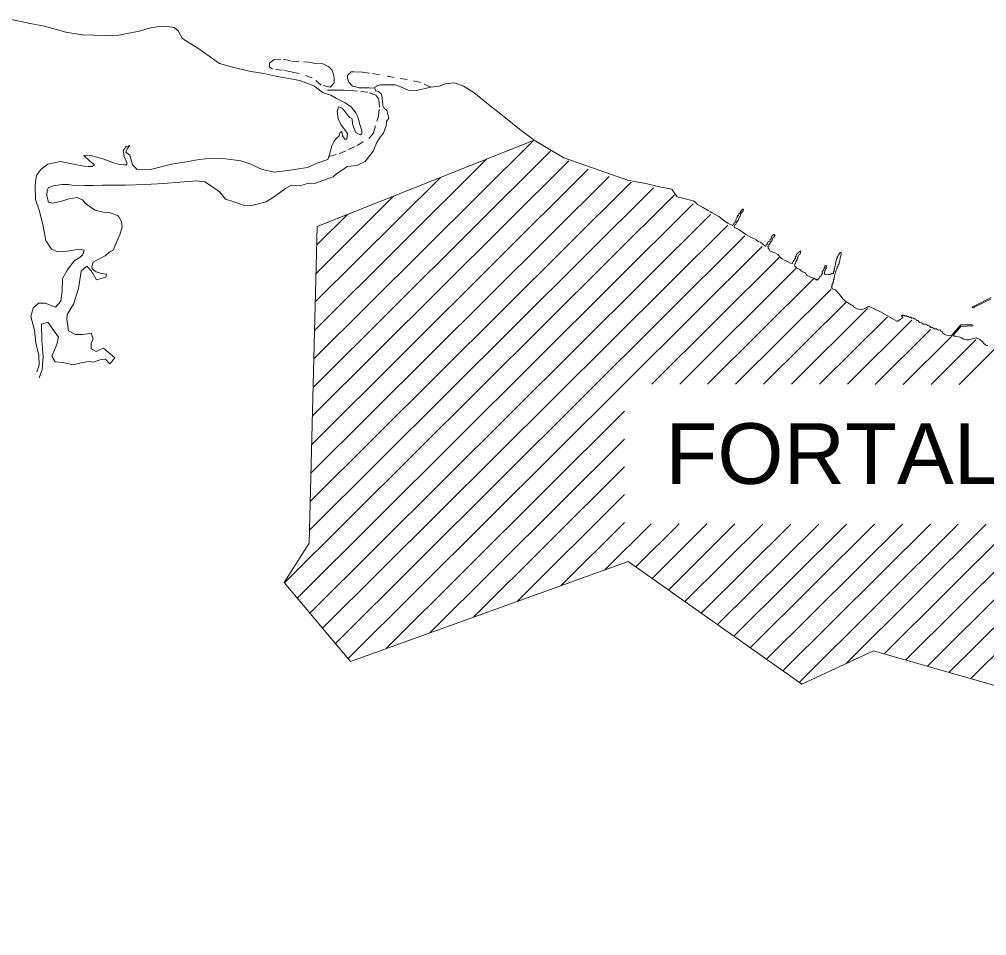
# Model space of a CAD drawing. Extents: x 47169 to 972804, y 7447977 to 9608469.
# Drawn here: x 541676 to 552551, y 9582149 to 9592447 of the extents above; entities that cross this region are included whole.
import ezdxf

# ---------------------------------------------------------------- set-up
doc = ezdxf.new("R2010")
doc.units = 0
doc.header["$LTSCALE"] = 270
doc.linetypes.add('DOTTED', pattern=[1.5, 0.3, -1.2])
doc.layers.add('1', color=7, linetype='Continuous', lineweight=13)
doc.layers.add('3', color=7, linetype='Continuous')

msp = doc.modelspace()

# ---------------------------------------------------------------- linework, layer by layer
at = {"layer": '1'}
for p, q in [((544987.1, 9588631.2), (547455.8, 9591086.2)), ((544978.1, 9588310.7), (547647.9, 9590965.6)), ((544970.2, 9587990.1), (547854.4, 9590857.2)), ((544995, 9588951.8), (546932.7, 9590878.7)), ((544962.2, 9587669.5), (548072, 9590762.1)), ((544954.3, 9587347.9), (548305.2, 9590681.2)), ((545002.9, 9589272.3), (546409.5, 9590671.1)), ((544937.4, 9586706.7), (548804.8, 9590552.8)), ((544946.4, 9587027.3), (548555, 9590617)), ((544655, 9586113.3), (549042.4, 9590476.4)), ((545010.9, 9589592.9), (545886.3, 9590463.5)), ((544798.2, 9585943), (549251.2, 9590372.4)), ((544941.4, 9585773.8), (549447.7, 9590255.1)), ((545018.8, 9589913.4), (545364.3, 9590256)), ((545084.5, 9585603.5), (549640.8, 9590134.5)), ((545228.8, 9585433.2), (549834, 9590013.9)), ((545372, 9585264), (550027.2, 9589893.3)), ((548786.2, 9588346.7), (550217, 9589769.4)), ((549100.5, 9588346.5), (550406.8, 9589645.5)), ((549413.7, 9588346.4), (550612.2, 9589538.2)), ((549727.9, 9588346.2), (550804.3, 9589416.5)), ((550043.3, 9588346), (550973, 9589270.5)), ((550356.5, 9588345.9), (551211.7, 9589196.3)), ((550670.8, 9588345.7), (551434.9, 9589105.6)), ((550985, 9588345.6), (551710.3, 9589066.7)), ((551299.3, 9588345.4), (551919, 9588961.6)), ((551613.6, 9588345.2), (552155.5, 9588884.1)), ((551926.7, 9588345.1), (552428.7, 9588844.2)), ((552241, 9588344.9), (552651.8, 9588753.4)), ((545798.5, 9585375.5), (548481.2, 9588043.3)), ((546290.5, 9585552.1), (548481, 9587730.5)), ((546782.5, 9585729.8), (548480.9, 9587418.8)), ((547274.5, 9585906.4), (548480.7, 9587106)), ((547766.5, 9586083.1), (548480.6, 9586793.1)), ((548258.6, 9586259.7), (548778, 9586776.2)), ((548606.2, 9586292.7), (549092.3, 9586776.1)), ((548789.3, 9586163.2), (549405.4, 9586775.9)), ((548973.6, 9586033.8), (549719.7, 9586775.8)), ((549157.9, 9585903.3), (550035.1, 9586775.6)), ((549341, 9585773.9), (550348.2, 9586775.5)), ((549525.3, 9585644.5), (550662.5, 9586775.3)), ((549709.6, 9585515), (550976.8, 9586775.1)), ((549892.7, 9585385.6), (551289.9, 9586775)), ((550077, 9585255.1), (551605.3, 9586774.8)), ((550261.3, 9585125.6), (551919.6, 9586774.6)), ((550444.4, 9584996.2), (552232.7, 9586774.5)), ((550970.9, 9585207.1), (552547, 9586774.3)), ((551397.4, 9585318.5), (552861.2, 9586774.1)), ((551641.6, 9585248.7), (553175.5, 9586774)), ((551884.8, 9585179), (553489.6, 9586773.8)), ((552129.1, 9585109.2), (553803.9, 9586773.6)), ((552373.3, 9585038.3), (554117.4, 9586773.4))]:
    msp.add_line(p, q, dxfattribs=at)
for points in [[(541996.8, 9590821.7), (542139.6, 9590851), (542284, 9590820), (542401.7, 9590795.6), (542449.4, 9590794.5), (542495, 9590793.3), (542520.5, 9590813.2), (542462.8, 9590858.6), (542399.5, 9590918.3), (542467.3, 9590919.4), (542626.1, 9590877.3), (542733.8, 9590834.2), (542788.2, 9590818.6), (542849.2, 9590814.2), (542882.6, 9590813.1), (542884.8, 9590842.9), (542859.3, 9590889.4), (542843.8, 9590970.1), (542874.9, 9591017.6), (542919.3, 9591028.6), (542893.8, 9591004.3), (542873.8, 9590955.7), (542919.2, 9590919.2), (542948.1, 9590814.2), (542999.2, 9590758.9), (543165.7, 9590762.1), (543385.6, 9590819.5), (543532.2, 9590841.5), (543697.7, 9590873.5), (543839.9, 9590888.9), (543994.2, 9590881.1), (544167.4, 9590857.8), (544265.2, 9590823.5), (544407.3, 9590761.6), (544542.8, 9590729.4), (544719.3, 9590752.6), (544914.8, 9590782.3), (545022.5, 9590832), (545142.5, 9590872.9), (545161.4, 9590928.1), (545189.2, 9591024.3), (545214.8, 9591077.3), (545240.3, 9591110.5), (545270.3, 9591139.2), (545277, 9591172.4), (545301.4, 9591186.7), (545307, 9591139.2), (545334.7, 9591099.4), (545358, 9591102.7), (545365.8, 9591163.5), (545290.4, 9591266.3), (545261.5, 9591328.2), (545247.1, 9591411.2), (545264.9, 9591465.3), (545306, 9591448.7), (545341.5, 9591403.4), (545372.6, 9591361.3), (545392.6, 9591344.8), (545417, 9591330.4), (545421.4, 9591272.9), (545455.8, 9591178.9), (545508, 9591151.3), (545524.6, 9591162.3), (545524.7, 9591197.7), (545501.4, 9591278.4), (545485.9, 9591340.3), (545458.1, 9591397.8), (545406, 9591464.1), (545331.6, 9591511.7), (545242.8, 9591557.1), (545176.1, 9591593.6), (545091.8, 9591621.2), (544985.2, 9591699.8), (544830.8, 9591758.4), (544559.9, 9591807.2), (544425.5, 9591837.1), (544280.1, 9591861.5), (544226.8, 9591872.6), (544102.4, 9591903.6), (543924.7, 9591952.3), (543811.5, 9592033), (543681.6, 9592123.7), (543603.9, 9592171.3), (543548.4, 9592204.5), (543505.1, 9592235.4), (543459.6, 9592319.5), (543415.2, 9592356), (543364.1, 9592364.8), (543267.5, 9592370.4), (543135.3, 9592347.2), (543040.9, 9592319.7), (542794.3, 9592271.1), (542638.9, 9592265.7), (542382.3, 9592272.4), (542198, 9592302.3), (541957.1, 9592371), (541796, 9592402), (541586.2, 9592447.4)], [(549250.1, 9590407.7), (549072.4, 9590454.2), (549012.5, 9590540.5), (548873.7, 9590563.8), (548719.3, 9590602.6), (548527.2, 9590638), (548409.5, 9590679), (548043.1, 9590804.1), (547798.9, 9590889.3), (547575.7, 9591023.2), (547463.6, 9591089.5), (547300.4, 9591212.3), (547123.9, 9591357.2), (546970.7, 9591474.5), (546786.4, 9591624.9), (546667.6, 9591695.7), (546568.8, 9591733.3), (546464.4, 9591723.4), (546396.7, 9591695.8), (546302.2, 9591684.8), (546142.3, 9591648.4), (546046.8, 9591652.9), (545965.8, 9591688.3), (545900.2, 9591710.4), (545794.8, 9591711.6), (545734.8, 9591710.5), (545694.8, 9591700.6), (545694.8, 9591696.1), (545673.7, 9591686.2), (545672.6, 9591675.1), (545678.1, 9591644.2), (545713.7, 9591635.3), (545748.1, 9591605.5), (545753.6, 9591559), (545758, 9591530.3), (545758, 9591528.1), (545762.4, 9591480.6), (545776.9, 9591448.5), (545805.7, 9591421.9), (545827.9, 9591337.9), (545802.3, 9591299.2), (545799, 9591251.7), (545771.2, 9591168.8), (545732.3, 9591122.4), (545694.5, 9591061.6), (545652.3, 9590965.5), (545563.4, 9590851.7), (545471.2, 9590805.3), (545364.6, 9590792.1), (545245.7, 9590713.6), (545203.5, 9590676.1), (545100.2, 9590640.8), (544993.6, 9590604.3), (544926.9, 9590605.5), (544828.1, 9590575.7), (544735.9, 9590585.7), (544667, 9590545.9), (544554.8, 9590465.2), (544451.5, 9590396.8), (544289.4, 9590353.7), (544195, 9590360.4), (544086.2, 9590396.9), (543991.8, 9590425.7), (543924.1, 9590509.7), (543846.4, 9590565.1), (543760.9, 9590620.3), (543666.5, 9590633.7), (543478.8, 9590616.1), (543296.7, 9590602.9), (543090.1, 9590590.8), (542868, 9590585.4), (542659.2, 9590583.3), (542611.5, 9590583.3), (542504.9, 9590578.9), (542411.6, 9590578.9), (542263.9, 9590583.4), (542232.8, 9590592.3), (542158.4, 9590592.3), (542054, 9590575.8), (542001.8, 9590557), (541987.4, 9590526.1), (541986.2, 9590463.1), (542001.8, 9590391.2), (542049.5, 9590382.3), (542165, 9590406.6), (542232.7, 9590432), (542327.2, 9590446.3), (542383.8, 9590417.6), (542417.1, 9590383.3), (542477, 9590336.8), (542529.2, 9590301.4), (542620.3, 9590280.4), (542692.4, 9590271.5), (542724.6, 9590266), (542777.9, 9590242.8), (542795.7, 9590228.4), (542823.4, 9590176.4), (542830.1, 9590110.1), (542806.7, 9590029.4), (542760, 9589923.3), (542730, 9589854.8)], [(557927.8, 9588750.4), (558195.3, 9588397.6), (559210.8, 9585590.4), (558211.2, 9585310.2), (556763.8, 9586414.3), (554189.6, 9582179.8), (553295.6, 9582149.4), (553111.7, 9582905.6), (553425.9, 9582840.2), (553310.4, 9584770.3), (551280.8, 9585351.7), (550474.4, 9584975.2), (548519.6, 9586353.5), (545398.6, 9585231.9), (544651.7, 9586116.6), (544934, 9586558.6), (545024.4, 9590121.2), (547463.6, 9591089.5)], [(541872.1, 9588485.6), (541898.8, 9588559.6), (541893.3, 9588671.3), (541861.2, 9588811.7), (541845.7, 9588953.2), (541805.8, 9589106.8), (541830.2, 9589200.8), (541889.1, 9589256), (541966.8, 9589256), (542081.2, 9589211.7), (542141.2, 9589280.2), (542155.7, 9589391.9), (542161.3, 9589536.7), (542215.8, 9589632.8), (542293.5, 9589732.3), (542355.7, 9589770.9), (542390.2, 9589805.2), (542404.6, 9589854.9), (542352.4, 9589863.8), (542213.6, 9589840.6), (542109.2, 9589836.2), (542037.1, 9589863.9), (541972.7, 9589961.2), (541941.7, 9590121.5), (541901.8, 9590291.8), (541858.5, 9590423.3), (541853, 9590577), (541859.7, 9590643.3), (541868.6, 9590693), (541911.9, 9590754.9), (541937.5, 9590775.9), (541996.8, 9590821.7)], [(550106, 9589863.5), (550094.9, 9589875.6), (550089.4, 9589882.3), (550093.8, 9589884.5), (550091.6, 9589893.3), (550103.8, 9589899.9), (550103.8, 9589914.3), (550116, 9589933.1), (550120.5, 9589938.6), (550128.3, 9589950.8), (550134.9, 9589958.5), (550140.5, 9589965.1), (550143.8, 9589979.5), (550149.4, 9589996.1), (550157.2, 9590000.5), (550166.1, 9590010.4), (550172.7, 9590018.2), (550164.9, 9590018.2), (550165, 9590029.2), (550152.7, 9590030.3), (550149.4, 9590021.5), (550139.4, 9590016), (550134.9, 9590001.6), (550131.6, 9590000.5), (550123.8, 9589972.9), (550117.2, 9589975.1), (550112.7, 9589955.2), (550093.8, 9589949.7), (550087.2, 9589933.1), (550083.8, 9589933.1), (550081.6, 9589913.2), (550071.6, 9589913.2), (550067.2, 9589897.7), (550059.4, 9589900), (550036.1, 9589919.9), (550008.3, 9589942), (549983.9, 9589952), (549958.4, 9589969.7), (549933.9, 9589986.2), (549905.1, 9589997.3), (549869.6, 9590012.8), (549841.8, 9590029.4), (549816.3, 9590047.1), (549766.3, 9590084.7), (549734.1, 9590100.2), (549718.6, 9590104.6), (549714.1, 9590116.8), (549720.8, 9590137.8), (549733, 9590143.3), (549735.2, 9590158.8), (549751.9, 9590185.3), (549761.9, 9590194.1), (549763, 9590205.2), (549765.3, 9590208.5), (549770.8, 9590227.3), (549780.8, 9590236.1), (549787.5, 9590260.5), (549803.1, 9590284.8), (549810.8, 9590284.8), (549813.1, 9590296.9), (549816.4, 9590309.1), (549811.9, 9590312.4), (549800.8, 9590312.4), (549797.5, 9590296.9), (549784.2, 9590293.6), (549781.9, 9590277), (549769.7, 9590266), (549761.9, 9590243.9), (549755.3, 9590245), (549754.2, 9590240.6), (549747.5, 9590226.2), (549743.1, 9590215.2), (549739.7, 9590210.7), (549733, 9590195.2), (549730.8, 9590179.8), (549723, 9590176.5), (549719.7, 9590158.8), (549710.8, 9590158.8), (549706.4, 9590144.4), (549695.3, 9590132.3), (549665.3, 9590146.7), (549646.4, 9590152.2), (549607.6, 9590177.6), (549578.7, 9590200.9), (549539.8, 9590231.8), (549517.6, 9590242.9), (549464.3, 9590273.9), (549446.6, 9590282.7), (549421, 9590300.4), (549356.7, 9590338.1), (549301.1, 9590367.9), (549280.1, 9590385.6), (549268.9, 9590397.8), (549250.1, 9590407.7)], [(542730, 9589854.8), (542686.7, 9589829.4), (542641.1, 9589789.6), (542553.4, 9589744.3), (542505.6, 9589716.7), (542491.2, 9589670.3), (542494.5, 9589642.7), (542540, 9589608.3), (542595.5, 9589592.9), (542655.5, 9589585.1), (542656.6, 9589579.6), (542646.6, 9589550.8), (542544.4, 9589521), (542487.8, 9589618.3), (542433.4, 9589673.6), (542369, 9589616.2), (542341.1, 9589422.7), (542283.3, 9589247), (542212.2, 9589129.9), (542209.9, 9589079), (542227.7, 9588948.6), (542306.5, 9588905.4), (542388.7, 9588905.4), (542468.6, 9588917.5), (542484.2, 9588919.7), (542505.2, 9588853.4), (542483, 9588810.3), (542483, 9588744), (542537.4, 9588713), (542622.9, 9588753.8), (542748.4, 9588644.4), (542693.9, 9588577), (542642.8, 9588628.9), (542594, 9588623.4), (542504, 9588593.6), (542461.8, 9588603.6), (542386.3, 9588590.4), (542280.8, 9588563.9), (542163.1, 9588591.6), (542078.7, 9588597.1), (542039.9, 9588661.3), (542098.8, 9588793.9), (542116.6, 9588876.8), (541994.5, 9589046), (541925.6, 9589020.6), (541930, 9588838.2), (541942.2, 9588656.9), (541932.1, 9588511), (541899.8, 9588420.3)], [(550864.4, 9589743.7), (550856.6, 9589722.7), (550850, 9589705), (550850, 9589687.3), (550843.3, 9589675.2), (550844.4, 9589661.9), (550837.7, 9589645.3), (550839.9, 9589634.3), (550834.4, 9589627.6), (550835.5, 9589617.7), (550828.8, 9589611.1), (550831, 9589604.4), (550829.9, 9589602.2), (550827.7, 9589590), (550811, 9589590.1), (550793.3, 9589581.2), (550773.3, 9589580.1), (550748.8, 9589577.9), (550734.4, 9589581.2), (550725.5, 9589596.7), (550727.8, 9589597.8), (550727.8, 9589604.5), (550727.8, 9589605.6), (550733.3, 9589615.5), (550733.3, 9589624.4), (550738.9, 9589628.8), (550741.1, 9589639.8), (550746.7, 9589648.7), (550747.8, 9589658.6), (550750, 9589671.9), (550745.6, 9589682.9), (550727.8, 9589678.5), (550734.5, 9589665.3), (550721.1, 9589644.3), (550720, 9589629.9), (550714.4, 9589624.4), (550702.2, 9589610), (550705.6, 9589591.2), (550695.6, 9589578), (550691.1, 9589562.5), (550682.2, 9589562.5), (550670, 9589549.2), (550665.5, 9589531.5), (550658.9, 9589532.7), (550646.7, 9589517.2), (550607.8, 9589537.1), (550570.1, 9589549.3), (550532.3, 9589567), (550509, 9589598), (550480.1, 9589611.2), (550463.5, 9589625.6), (550452.4, 9589634.5), (550435.7, 9589643.3), (550417.9, 9589651.1), (550409.1, 9589658.8), (550398, 9589669.8), (550391.3, 9589677.6), (550389.1, 9589682), (550393.6, 9589689.8), (550394.7, 9589698.6), (550403.6, 9589705.2), (550405.8, 9589725.1), (550420.2, 9589748.3), (550420.2, 9589760.5), (550426.9, 9589771.5), (550428, 9589776), (550441.3, 9589801.4), (550449.1, 9589804.7), (550449.1, 9589813.5), (550456.9, 9589815.7), (550458, 9589829), (550460.2, 9589840.1), (550453.6, 9589844.5), (550453.6, 9589843.4), (550450.2, 9589834.5), (550442.5, 9589837.8), (550436.9, 9589823.5), (550426.9, 9589823.5), (550422.5, 9589809.1), (550414.7, 9589808), (550410.2, 9589787), (550400.2, 9589779.3), (550400.2, 9589761.6), (550391.3, 9589750.6), (550391.3, 9589741.7), (550380.2, 9589737.3), (550380.2, 9589725.1), (550370.2, 9589720.7), (550369.1, 9589707.5), (550364.7, 9589699.7), (550345.8, 9589707.5), (550315.8, 9589721.9), (550279.2, 9589741.8), (550253.7, 9589756.2), (550229.2, 9589773.8), (550204.8, 9589803.7), (550195.9, 9589809.2), (550170.4, 9589823.6), (550141.5, 9589833.6), (550116, 9589843.6), (550106, 9589863.5)], [(552010.1, 9588953.8), (551997.8, 9588960.5), (551987.9, 9588968.2), (551961.2, 9588968.2), (551942.3, 9588984.8), (551924.6, 9588984.8), (551903.5, 9589003.6), (551890.2, 9589008.1), (551869.1, 9589020.2), (551838, 9589022.5), (551819.1, 9589036.8), (551796.9, 9589041.3), (551779.1, 9589061.2), (551766.9, 9589067.8), (551760.3, 9589066.7), (551754.7, 9589080), (551743.6, 9589078.9), (551735.8, 9589080), (551721.4, 9589092.2), (551710.3, 9589087.7), (551697, 9589102.1), (551690.3, 9589102.1), (551684.8, 9589098.8), (551681.4, 9589097.7), (551678.1, 9589102.1), (551667, 9589108.8), (551657, 9589107.7), (551650.3, 9589115.4), (551638.1, 9589116.5), (551634.8, 9589113.2), (551628.1, 9589120.9), (551620.4, 9589117.6), (551617, 9589123.2), (551611.5, 9589124.3), (551602.6, 9589122.1), (551594.8, 9589112.1), (551595.9, 9589108.8), (551603.7, 9589107.7), (551603.7, 9589104.4), (551608.1, 9589096.6), (551594.8, 9589086.7), (551582.6, 9589079), (551552.6, 9589055.8), (551542.6, 9589054.7), (551358.3, 9589158.7), (551238.4, 9589217.3), (551220.6, 9589218.4), (551204, 9589209.6), (551181.8, 9589197.4), (551149.5, 9589184.2), (551095.1, 9589193.1), (551059.6, 9589214.1), (551054.1, 9589224.1), (551009.7, 9589250.6), (550965.2, 9589274.9), (550956.4, 9589286), (550937.5, 9589303.7), (550913.1, 9589338), (550888.7, 9589365.6), (550863.1, 9589394.4), (550850.9, 9589408.8), (550818.7, 9589418.7), (550808.7, 9589428.7), (550807.6, 9589441.9), (550813.2, 9589449.7), (550812.1, 9589465.2), (550823.2, 9589476.2), (550822.1, 9589487.2), (550829.9, 9589498.3), (550829.9, 9589520.4), (550837.7, 9589531.5), (550836.6, 9589548), (550842.1, 9589556.9), (550841, 9589573.5), (550845.5, 9589580.1), (550846.6, 9589596.7), (550852.1, 9589603.3), (550854.4, 9589621), (550861, 9589627.6), (550863.3, 9589643.1), (550871, 9589648.6), (550872.2, 9589669.6), (550879.9, 9589674), (550881.1, 9589693.9), (550892.2, 9589699.4), (550892.2, 9589717.1), (550901.1, 9589735.9), (550904.4, 9589766.9), (550911.1, 9589791.2), (550914.4, 9589804.5), (550914.4, 9589819.9), (550908.9, 9589829.9), (550906.7, 9589822.1), (550897.8, 9589822.1), (550897.8, 9589815.5), (550884.4, 9589802.3), (550883.3, 9589791.2), (550871.1, 9589782.4), (550874.4, 9589771.3), (550863.3, 9589754.7), (550864.4, 9589743.7)], [(552603.3, 9589320.5), (552410, 9589222.2), (552403.3, 9589224.4), (552393.3, 9589221.1), (552390, 9589212.3), (552393.3, 9589204.6), (552398.9, 9589203.4), (552408.9, 9589206.8), (552411.1, 9589211.2), (552598.8, 9589301.7)], [(552565.2, 9588783.3), (552548.6, 9588781.1), (552525.3, 9588795.5), (552501.9, 9588826.4), (552474.2, 9588847.5), (552434.2, 9588866.3), (552402, 9588860.8), (552374.2, 9588851.9), (552350.9, 9588846.4), (552325.4, 9588846.4), (552292.1, 9588853.1), (552271, 9588866.3), (552248.8, 9588877.4), (552216.6, 9588881.9), (552204.4, 9588888.5), (552181.1, 9588888.5), (552169.9, 9588890.7), (552262.2, 9588995.7), (552394.3, 9589003.4), (552396.5, 9589005.6), (552396.6, 9589011.1), (552383.2, 9589015.5), (552349.9, 9589014.4), (552285.5, 9589013.4), (552262.2, 9589013.4), (552152.2, 9588889.6), (552100, 9588898.5), (552074.4, 9588908.5), (552065.6, 9588916.2), (552054.5, 9588922.8), (552055.6, 9588935), (552036.7, 9588939.5), (552031.2, 9588958.2), (552010.1, 9588953.8)]]:
    msp.add_lwpolyline(points, dxfattribs=at)
at = {"layer": '1', "linetype": 'DOTTED'}
msp.add_lwpolyline([(544872, 9591971.8), (544929.8, 9591966.2), (545005.3, 9591952.9), (545093, 9591946.2), (545156.3, 9591914.1), (545188.5, 9591881), (545206.2, 9591832.3), (545216.2, 9591785.9), (545214, 9591732.8), (545171.7, 9591685.3), (545070.7, 9591707.5), (544968.6, 9591791.5), (544822, 9591840.2), (544734.3, 9591856.8), (544641, 9591875.7), (544522.2, 9591889), (544487.8, 9591913.3), (544487.8, 9591956.4), (544538.9, 9591995.1), (544644.4, 9591999.5), (544737.7, 9591976.2)], close=True, dxfattribs=at)
for points in [[(546302.2, 9591684.8), (546185.7, 9591736.8), (546036.9, 9591771.1), (545890.3, 9591794.4), (545726, 9591823.2), (545612.7, 9591844.3), (545531.6, 9591852.1), (545438.3, 9591857.6), (545406.1, 9591857.7), (545365, 9591817.9), (545365, 9591784.7), (545379.4, 9591740.5), (545422.7, 9591695.1), (545446, 9591694), (545493.8, 9591677.4), (545559.3, 9591677.4), (545608.2, 9591676.3), (545672.6, 9591675.1)], [(545161.4, 9590928.1), (545159.2, 9590907.1), (545270.2, 9590936.9), (545376.9, 9590983.3), (545472.4, 9591030.8), (545604.6, 9591107), (545659, 9591172.2), (545693.5, 9591301.5), (545714.6, 9591359), (545724.7, 9591460.7), (545716.9, 9591550.2), (545684.8, 9591595.5), (545593.7, 9591628.7), (545479.3, 9591642.1), (545402.7, 9591646.5), (545328.3, 9591649.9), (545257.2, 9591649.9), (545195, 9591651), (545141.7, 9591652.2)]]:
    msp.add_lwpolyline(points, dxfattribs=at)

# ---------------------------------------------------------------- texts
at = {"layer": '3', "width": 1.05}
msp.add_text('FORTALEZA', height=681.6, dxfattribs=at).set_placement((548938.7, 9587226.6))

doc.saveas('drawing.dxf')
